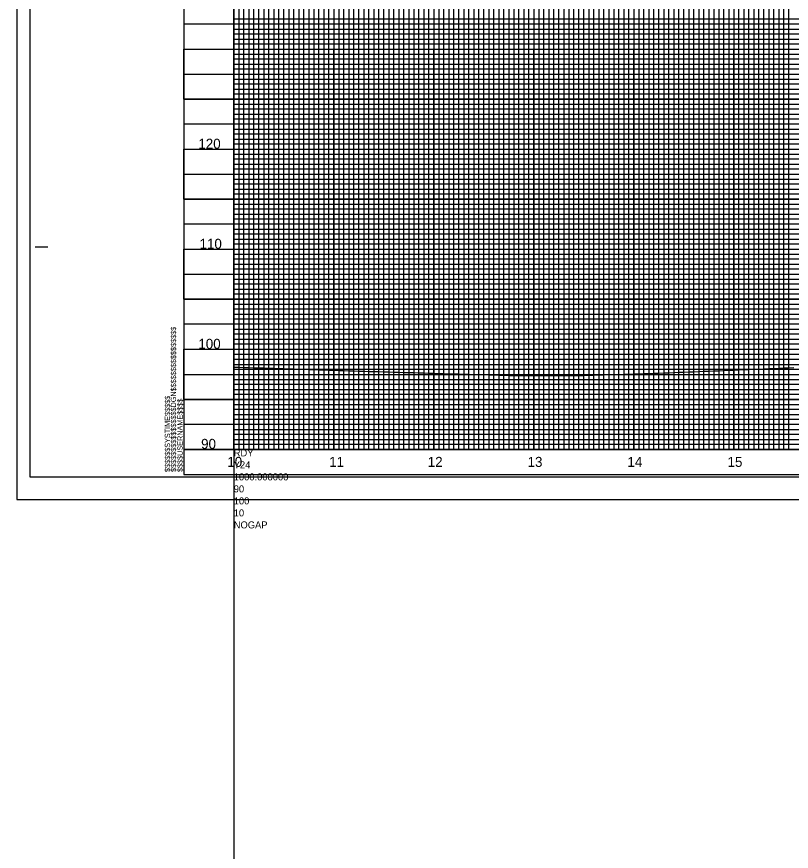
# Model space of a CAD drawing. Extents: x 2345490 to 2436403, y 465165 to 573888.
# Drawn here: x 2381550 to 2382324, y 514736 to 515570 of the extents above; entities that cross this region are included whole.
import ezdxf

# ---------------------------------------------------------------- set-up
doc = ezdxf.new("R2010")
doc.units = 0
for name, color, linetype in [('Old_Level_1', 7, 'Continuous'), ('Old_Level_18', 7, 'Continuous'), ('Old_Level_40', 7, 'Continuous'), ('Old_Level_41', 7, 'Continuous'), ('Old_Level_42', 7, 'Continuous'), ('Old_Level_43', 7, 'Continuous'), ('Old_Level_50', 7, 'Continuous'), ('Old_Level_51', 7, 'Continuous'), ('Old_Level_52', 7, 'Continuous'), ('Old_Level_57', 7, 'Continuous'), ('Old_Level_62', 7, 'Continuous'), ('Old_Level_63', 7, 'Continuous')]:
    doc.layers.add(name, color=color, linetype=linetype)

msp = doc.modelspace()

# ---------------------------------------------------------------- linework, layer by layer
at = {"layer": 'Old_Level_1'}
for points in [[(2381766.799, 515219.7965), (2381771.799, 515219.64425), (2381776.799, 515219.492), (2381781.799, 515219.3395), (2381786.799, 515219.18725), (2381791.799, 515219.03475), (2381796.799, 515218.8825), (2381801.799, 515218.73), (2381806.799, 515218.57775), (2381811.799, 515218.42525), (2381816.799, 515218.27275), (2381821.799, 515218.11875), (2381826.799, 515217.96325), (2381831.799, 515217.80575), (2381836.799, 515217.64675), (2381841.799, 515217.48575), (2381846.799, 515217.32325), (2381851.799, 515217.15875), (2381856.799, 515216.9985), (2381861.799, 515216.833), (2381866.799, 515216.6655), (2381871.799, 515216.49625), (2381876.799, 515216.32525), (2381881.799, 515216.153), (2381886.799, 515215.997), (2381891.799, 515215.8265), (2381896.799, 515215.6525), (2381901.799, 515215.52375), (2381906.799, 515215.3815), (2381911.799, 515215.23825), (2381916.799, 515215.09375), (2381921.799, 515214.948), (2381926.799, 515214.80125), (2381931.799, 515214.66525), (2381936.799, 515214.515), (2381941.799, 515214.36375), (2381946.799, 515214.2115), (2381951.799, 515214.0585), (2381956.799, 515213.90425), (2381961.799, 515213.7525), (2381966.799, 515213.5965), (2381971.799, 515213.4395), (2381976.799, 515213.31125), (2381981.799, 515213.1845), (2381986.799, 515213.0565), (2381991.799, 515212.9185), (2381996.799, 515212.7805), (2382001.799, 515212.6425), (2382006.799, 515212.494), (2382011.799, 515212.35425), (2382016.799, 515212.2145), (2382021.799, 515212.075), (2382026.799, 515211.93575), (2382031.799, 515211.79675), (2382036.799, 515211.65025), (2382041.799, 515211.51175), (2382046.799, 515211.4825), (2382051.799, 515211.4645), (2382056.799, 515211.44675), (2382061.799, 515211.42925), (2382066.799, 515211.41175), (2382071.799, 515211.39125), (2382076.799, 515211.36525), (2382081.799, 515211.34875), (2382086.799, 515211.332), (2382091.799, 515211.3155), (2382096.799, 515211.299), (2382101.799, 515211.2825), (2382106.799, 515211.258), (2382111.799, 515211.2745), (2382116.799, 515211.42925), (2382121.799, 515211.584), (2382126.799, 515211.73875), (2382131.799, 515211.8935), (2382136.799, 515212.04825), (2382141.799, 515212.20225), (2382146.799, 515212.35725), (2382151.799, 515212.51225), (2382156.799, 515212.66575), (2382161.799, 515212.81625), (2382166.799, 515212.9665), (2382171.799, 515213.117), (2382176.799, 515213.2675), (2382181.799, 515213.418), (2382186.799, 515213.58875), (2382191.799, 515213.78875), (2382196.799, 515213.98875), (2382201.799, 515214.18875), (2382206.799, 515214.38875), (2382211.799, 515214.58875), (2382216.799, 515214.788), (2382221.799, 515214.988), (2382226.799, 515215.188), (2382231.799, 515215.388), (2382236.799, 515215.588), (2382241.799, 515215.78825), (2382246.799, 515215.988), (2382251.799, 515216.18825), (2382256.799, 515216.38875), (2382261.799, 515216.598), (2382266.799, 515216.807)], [(2382266.799, 515216.807), (2382271.799, 515217.016), (2382276.799, 515217.22525), (2382281.799, 515217.43425), (2382286.799, 515217.643), (2382291.799, 515217.85225), (2382296.799, 515218.06125), (2382301.799, 515218.27025), (2382306.799, 515218.47925), (2382311.799, 515218.68825), (2382316.799, 515218.897), (2382321.799, 515219.106), (2382326.799, 515219.315)]]:
    msp.add_lwpolyline(points, dxfattribs=at)
at = {"layer": 'Old_Level_18'}
msp.add_line((2381716.79875, 515112.5265), (2381716.79875, 515112.5265), dxfattribs=at)
msp.add_line((2381716.79875, 515112.5265), (2381716.79875, 515112.5265), dxfattribs=at)
msp.add_lwpolyline([(2383216.79875, 516162.5265), (2381716.79875, 516162.5265), (2381716.79875, 515112.5265), (2383216.79875, 515112.5265)], close=True, dxfattribs=at)
at = {"layer": 'Old_Level_40'}
msp.add_line((2381716.79875, 515112.5265), (2381716.79875, 515112.5265), dxfattribs=at)
msp.add_line((2381716.79875, 515112.5265), (2381716.79875, 515112.5265), dxfattribs=at)
msp.add_line((2381716.79875, 515112.5265), (2381716.79875, 515112.5265), dxfattribs=at)
msp.add_line((2381716.79875, 515112.5265), (2381716.79875, 515112.5265), dxfattribs=at)
at = {"layer": 'Old_Level_41'}
for p, q in [((2381568.29875, 515340.0265), (2381580.79875, 515340.0265)), ((2383216.79875, 515137.5265), (2381716.79875, 515137.5265))]:
    msp.add_line(p, q, dxfattribs=at)
for points in [[(2381766.79875, 516162.5265), (2381766.79875, 515137.5265), (2381816.79875, 515137.5265), (2381816.79875, 516162.5265)], [(2381791.79875, 515137.5265), (2381791.79875, 516162.5265)], [(2381841.79875, 516162.5265), (2381841.79875, 515137.5265), (2381891.79875, 515137.5265), (2381891.79875, 516162.5265)], [(2381866.79875, 516162.5265), (2381866.79875, 515137.5265), (2381916.79875, 515137.5265), (2381916.79875, 516162.5265)], [(2381941.79875, 516162.5265), (2381941.79875, 515137.5265), (2381991.79875, 515137.5265), (2381991.79875, 516162.5265)], [(2381966.79875, 516162.5265), (2381966.79875, 515137.5265), (2382016.79875, 515137.5265), (2382016.79875, 516162.5265)], [(2382041.79875, 516162.5265), (2382041.79875, 515137.5265), (2382091.79875, 515137.5265), (2382091.79875, 516162.5265)], [(2382066.79875, 516162.5265), (2382066.79875, 515137.5265), (2382116.79875, 515137.5265), (2382116.79875, 516162.5265)], [(2382141.79875, 516162.5265), (2382141.79875, 515137.5265), (2382191.79875, 515137.5265), (2382191.79875, 516162.5265)], [(2382166.79875, 516162.5265), (2382166.79875, 515137.5265), (2382216.79875, 515137.5265), (2382216.79875, 516162.5265)], [(2382241.79875, 516162.5265), (2382241.79875, 515137.5265), (2382291.79875, 515137.5265), (2382291.79875, 516162.5265)], [(2382266.79875, 516162.5265), (2382266.79875, 515137.5265), (2382316.79875, 515137.5265), (2382316.79875, 516162.5265)], [(2383216.79875, 515562.5265), (2381716.79875, 515562.5265), (2381716.79875, 515512.5265), (2383216.79875, 515512.5265)], [(2383216.79875, 515487.5265), (2381716.79875, 515487.5265), (2381716.79875, 515537.5265), (2383216.79875, 515537.5265)], [(2383216.79875, 515462.5265), (2381716.79875, 515462.5265), (2381716.79875, 515412.5265), (2383216.79875, 515412.5265)], [(2383216.79875, 515387.5265), (2381716.79875, 515387.5265), (2381716.79875, 515437.5265), (2383216.79875, 515437.5265)], [(2383216.79875, 515362.5265), (2381716.79875, 515362.5265), (2381716.79875, 515312.5265), (2383216.79875, 515312.5265)], [(2383216.79875, 515262.5265), (2381716.79875, 515262.5265), (2381716.79875, 515212.5265), (2383216.79875, 515212.5265)], [(2383216.79875, 515187.5265), (2381716.79875, 515187.5265), (2381716.79875, 515237.5265), (2383216.79875, 515237.5265)], [(2383216.79875, 515162.5265), (2381716.79875, 515162.5265)], [(2381754.29875, 515112.5265), (2381754.29875, 515112.5265)]]:
    msp.add_lwpolyline(points, dxfattribs=at)
at = {"layer": 'Old_Level_42'}
msp.add_lwpolyline([(2383216.79875, 515287.5265), (2381716.79875, 515287.5265), (2381716.79875, 515337.5265), (2383216.79875, 515337.5265)], dxfattribs=at)
at = {"layer": 'Old_Level_43'}
for points in [[(2381771.79875, 516162.5265), (2381771.79875, 515137.5265), (2381776.79875, 515137.5265), (2381776.79875, 516162.5265)], [(2381781.79875, 516162.5265), (2381781.79875, 515137.5265), (2381786.79875, 515137.5265), (2381786.79875, 516162.5265)], [(2381796.79875, 516162.5265), (2381796.79875, 515137.5265), (2381801.79875, 515137.5265), (2381801.79875, 516162.5265)], [(2381806.79875, 516162.5265), (2381806.79875, 515137.5265), (2381811.79875, 515137.5265), (2381811.79875, 516162.5265)], [(2381821.79875, 516162.5265), (2381821.79875, 515137.5265), (2381826.79875, 515137.5265), (2381826.79875, 516162.5265)], [(2381831.79875, 516162.5265), (2381831.79875, 515137.5265), (2381836.79875, 515137.5265), (2381836.79875, 516162.5265)], [(2381846.79875, 516162.5265), (2381846.79875, 515137.5265), (2381851.79875, 515137.5265), (2381851.79875, 516162.5265)], [(2381856.79875, 516162.5265), (2381856.79875, 515137.5265), (2381861.79875, 515137.5265), (2381861.79875, 516162.5265)], [(2381871.79875, 516162.5265), (2381871.79875, 515137.5265), (2381876.79875, 515137.5265), (2381876.79875, 516162.5265)], [(2381881.79875, 516162.5265), (2381881.79875, 515137.5265), (2381886.79875, 515137.5265), (2381886.79875, 516162.5265)], [(2381896.79875, 516162.5265), (2381896.79875, 515137.5265), (2381901.79875, 515137.5265), (2381901.79875, 516162.5265)], [(2381906.79875, 516162.5265), (2381906.79875, 515137.5265), (2381911.79875, 515137.5265), (2381911.79875, 516162.5265)], [(2381921.79875, 516162.5265), (2381921.79875, 515137.5265), (2381926.79875, 515137.5265), (2381926.79875, 516162.5265)], [(2381931.79875, 515137.5265), (2381936.79875, 515137.5265), (2381936.79875, 516162.5265)], [(2381931.79875, 516162.5265), (2381931.79875, 515137.5265)], [(2381946.79875, 516162.5265), (2381946.79875, 515137.5265), (2381951.79875, 515137.5265), (2381951.79875, 516162.5265)], [(2381956.79875, 516162.5265), (2381956.79875, 515137.5265), (2381961.79875, 515137.5265), (2381961.79875, 516162.5265)], [(2381971.79875, 516162.5265), (2381971.79875, 515137.5265), (2381976.79875, 515137.5265), (2381976.79875, 516162.5265)], [(2381981.79875, 516162.5265), (2381981.79875, 515137.5265), (2381986.79875, 515137.5265), (2381986.79875, 516162.5265)], [(2381996.79875, 516162.5265), (2381996.79875, 515137.5265), (2382001.79875, 515137.5265), (2382001.79875, 516162.5265)], [(2382006.79875, 516162.5265), (2382006.79875, 515137.5265), (2382011.79875, 515137.5265), (2382011.79875, 516162.5265)], [(2382021.79875, 516162.5265), (2382021.79875, 515137.5265), (2382026.79875, 515137.5265), (2382026.79875, 516162.5265)], [(2382031.79875, 516162.5265), (2382031.79875, 515137.5265), (2382036.79875, 515137.5265), (2382036.79875, 516162.5265)], [(2382046.79875, 516162.5265), (2382046.79875, 515137.5265), (2382051.79875, 515137.5265), (2382051.79875, 516162.5265)], [(2382056.79875, 516162.5265), (2382056.79875, 515137.5265), (2382061.79875, 515137.5265), (2382061.79875, 516162.5265)], [(2382071.79875, 516162.5265), (2382071.79875, 515137.5265), (2382076.79875, 515137.5265), (2382076.79875, 516162.5265)], [(2382081.79875, 516162.5265), (2382081.79875, 515137.5265), (2382086.79875, 515137.5265), (2382086.79875, 516162.5265)], [(2382096.79875, 516162.5265), (2382096.79875, 515137.5265), (2382111.79875, 515137.5265), (2382111.79875, 516162.5265)], [(2382101.79875, 516162.5265), (2382101.79875, 515137.5265), (2382106.79875, 515137.5265), (2382106.79875, 516162.5265)], [(2382101.79875, 516161.9265), (2382101.79875, 515137.5265), (2382106.79875, 515137.5265), (2382106.79875, 516161.9265)], [(2382121.79875, 516162.5265), (2382121.79875, 515137.5265), (2382126.79875, 515137.5265), (2382126.79875, 516162.5265)], [(2382131.79875, 516162.5265), (2382131.79875, 515137.5265), (2382136.79875, 515137.5265), (2382136.79875, 516162.5265)], [(2382146.79875, 516162.5265), (2382146.79875, 515137.5265), (2382151.79875, 515137.5265), (2382151.79875, 516162.5265)], [(2382156.79875, 516162.5265), (2382156.79875, 515137.5265), (2382161.79875, 515137.5265), (2382161.79875, 516162.5265)], [(2382171.79875, 516162.5265), (2382171.79875, 515137.5265), (2382176.79875, 515137.5265), (2382176.79875, 516162.5265)], [(2382181.79875, 516162.5265), (2382181.79875, 515137.5265), (2382186.79875, 515137.5265), (2382186.79875, 516162.5265)], [(2382196.79875, 516162.5265), (2382196.79875, 515137.5265), (2382201.79875, 515137.5265), (2382201.79875, 516162.5265)], [(2382206.79875, 516162.5265), (2382206.79875, 515137.5265), (2382211.79875, 515137.5265), (2382211.79875, 516162.5265)], [(2382221.79875, 516162.5265), (2382221.79875, 515137.5265), (2382226.79875, 515137.5265), (2382226.79875, 516162.5265)], [(2382231.79875, 516162.5265), (2382231.79875, 515137.5265), (2382236.79875, 515137.5265), (2382236.79875, 516162.5265)], [(2382246.79875, 516162.5265), (2382246.79875, 515137.5265)], [(2382251.79875, 516162.5265), (2382251.79875, 515137.5265), (2382256.79875, 515137.5265), (2382256.79875, 516162.5265), (2382261.79875, 516162.5265), (2382261.79875, 515137.5265), (2382271.79875, 515137.5265), (2382271.79875, 516162.5265), (2382276.79875, 516162.5265), (2382276.79875, 515137.5265), (2382281.79875, 515137.5265), (2382281.79875, 516162.5265), (2382286.79875, 516162.5265), (2382286.79875, 515137.5265)], [(2382296.79875, 515137.5265), (2382296.79875, 516162.5265)], [(2382301.79875, 516162.5265), (2382301.79875, 515137.5265), (2382306.79875, 515137.5265), (2382306.79875, 516162.5265)], [(2382311.79875, 516162.5265), (2382311.79875, 515137.5265), (2382321.79875, 515137.5265), (2382321.79875, 516162.5265)], [(2383166.79875, 515567.5265), (2381766.79875, 515567.5265), (2381766.79875, 515557.5265), (2383166.79875, 515557.5265)], [(2383166.79875, 515552.5265), (2381766.79875, 515552.5265), (2381766.79875, 515547.5265), (2383166.79875, 515547.5265)], [(2383166.79875, 515542.5265), (2381766.79875, 515542.5265), (2381766.79875, 515532.5265), (2383166.79875, 515532.5265)], [(2383166.79875, 515527.5265), (2381766.79875, 515527.5265), (2381766.79875, 515522.5265), (2383166.79875, 515522.5265)], [(2383166.79875, 515517.5265), (2381766.79875, 515517.5265), (2381766.79875, 515507.5265), (2383166.79875, 515507.5265)], [(2383166.79875, 515502.5265), (2381766.79875, 515502.5265), (2381766.79875, 515497.5265), (2383166.79875, 515497.5265)], [(2383166.79875, 515492.5265), (2381766.79875, 515492.5265), (2381766.79875, 515482.5265), (2383166.79875, 515482.5265)], [(2383166.79875, 515477.5265), (2381766.79875, 515477.5265), (2381766.79875, 515472.5265), (2383166.79875, 515472.5265)], [(2383166.79875, 515467.5265), (2381766.79875, 515467.5265), (2381766.79875, 515457.5265), (2383166.79875, 515457.5265)], [(2383166.79875, 515452.5265), (2381766.79875, 515452.5265), (2381766.79875, 515447.5265), (2383166.79875, 515447.5265)], [(2383166.79875, 515442.5265), (2381766.79875, 515442.5265), (2381766.79875, 515432.5265), (2383166.79875, 515432.5265)], [(2383166.79875, 515427.5265), (2381766.79875, 515427.5265), (2381766.79875, 515422.5265), (2383166.79875, 515422.5265)], [(2383166.79875, 515417.5265), (2381766.79875, 515417.5265), (2381766.79875, 515407.5265), (2383166.79875, 515407.5265)], [(2383166.79875, 515402.5265), (2381766.79875, 515402.5265), (2381766.79875, 515397.5265), (2383166.79875, 515397.5265)], [(2383166.79875, 515392.5265), (2381766.79875, 515392.5265), (2381766.79875, 515382.5265), (2383166.79875, 515382.5265)], [(2383166.79875, 515377.5265), (2381766.79875, 515377.5265), (2381766.79875, 515372.5265), (2383166.79875, 515372.5265)], [(2383166.79875, 515367.5265), (2381766.79875, 515367.5265), (2381766.79875, 515357.5265), (2383166.79875, 515357.5265)], [(2383166.79875, 515352.5265), (2381766.79875, 515352.5265), (2381766.79875, 515347.5265), (2383166.79875, 515347.5265)], [(2383166.79875, 515342.5265), (2381766.79875, 515342.5265)], [(2381766.79875, 515332.5265), (2383166.79875, 515332.5265)], [(2383166.79875, 515327.5265), (2381766.79875, 515327.5265), (2381766.79875, 515322.5265), (2383166.79875, 515322.5265)], [(2383166.79875, 515317.5265), (2381766.79875, 515317.5265)], [(2381766.79875, 515307.5265), (2383166.79875, 515307.5265)], [(2383166.79875, 515302.5265), (2381766.79875, 515302.5265), (2381766.79875, 515297.5265), (2383166.79875, 515297.5265)], [(2383166.79875, 515292.5265), (2381766.79875, 515292.5265), (2381766.79875, 515282.5265), (2383166.79875, 515282.5265)], [(2383166.79875, 515277.5265), (2381766.79875, 515277.5265), (2381766.79875, 515272.5265), (2383166.79875, 515272.5265)], [(2383166.79875, 515267.5265), (2381766.79875, 515267.5265), (2381766.79875, 515257.5265), (2383166.79875, 515257.5265)], [(2383166.79875, 515252.5265), (2381766.79875, 515252.5265), (2381766.79875, 515247.5265), (2383166.79875, 515247.5265)], [(2383166.79875, 515242.5265), (2381766.79875, 515242.5265), (2381766.79875, 515232.5265), (2383166.79875, 515232.5265)], [(2383166.79875, 515227.5265), (2381766.79875, 515227.5265), (2381766.79875, 515222.5265), (2383166.79875, 515222.5265)], [(2383166.79875, 515217.5265), (2381766.79875, 515217.5265), (2381766.79875, 515207.5265), (2383166.79875, 515207.5265)], [(2383166.79875, 515202.5265), (2381766.79875, 515202.5265), (2381766.79875, 515197.5265), (2383166.79875, 515197.5265)], [(2383166.79875, 515192.5265), (2381766.79875, 515192.5265), (2381766.79875, 515182.5265), (2383166.79875, 515182.5265)], [(2383166.79875, 515177.5265), (2381766.79875, 515177.5265), (2381766.79875, 515172.5265), (2383166.79875, 515172.5265)], [(2383166.79875, 515167.5265), (2381766.79875, 515167.5265), (2381766.79875, 515157.5265), (2383166.79875, 515157.5265)], [(2383166.79875, 515152.5265), (2381766.79875, 515152.5265), (2381766.79875, 515147.5265), (2383166.79875, 515147.5265)], [(2383166.79875, 515142.5265), (2381766.79875, 515142.5265)]]:
    msp.add_lwpolyline(points, dxfattribs=at)
at = {"layer": 'Old_Level_50'}
msp.add_line((2381549.79875, 515087.5265), (2381549.79875, 515087.5265), dxfattribs=at)
msp.add_lwpolyline([(2383229.29875, 516165.0765), (2381562.79875, 516165.0765), (2381562.79875, 515109.9765), (2383229.29875, 515109.9765)], close=True, dxfattribs=at)
at = {"layer": 'Old_Level_51'}
msp.add_lwpolyline([(2383233.79875, 516187.5265), (2381549.79875, 516187.5265), (2381549.79875, 515087.5265), (2383233.79875, 515087.5265)], close=True, dxfattribs=at)
at = {"layer": 'Old_Level_52'}
msp.add_line((2381562.79875, 515109.9765), (2381562.79875, 515109.9765), dxfattribs=at)
at = {"layer": 'Old_Level_57'}
for p, q in [((2381716.79925, 515537.52675), (2386366.79875, 515537.52675)), ((2381766.79875, 515137.52675), (2381766.79875, 515537.52675)), ((2381866.79875, 515137.52675), (2381866.79875, 515537.52675)), ((2381966.79875, 515137.52675), (2381966.79875, 515537.52675)), ((2382066.79875, 515137.52675), (2382066.79875, 515537.52675)), ((2382166.79875, 515137.52675), (2382166.79875, 515537.52675)), ((2382166.79875, 515137.62675), (2382166.79875, 515537.52675)), ((2382266.79875, 515137.52675), (2382266.79875, 515537.52675)), ((2382266.79875, 515137.62675), (2382266.79875, 515537.52675)), ((2381716.79925, 515487.52675), (2386366.79875, 515487.52675)), ((2381716.79925, 515437.52675), (2386366.79875, 515437.52675)), ((2381716.79925, 515387.52675), (2386366.79875, 515387.52675)), ((2381716.79925, 515337.52675), (2386366.79875, 515337.52675)), ((2381716.79925, 515287.52675), (2386366.79875, 515287.52675)), ((2381716.79925, 515237.52675), (2386366.79875, 515237.52675)), ((2381716.799, 515187.52675), (2386366.79875, 515187.52675)), ((2381716.79925, 515137.52675), (2386366.79875, 515137.52675))]:
    msp.add_line(p, q, dxfattribs=at)
at = {"layer": 'Old_Level_63'}
for q in [(2381766.79875, 517637.5265), (2386228.05125, 515137.5265), (2381766.79875, 512637.5265)]:
    msp.add_line((2381766.79875, 515137.5265), q, dxfattribs=at)

# ---------------------------------------------------------------- texts
at = {"layer": 'Old_Level_41'}
for s, p in [('$$$$$$$$$$$$$$$$DGN$$$$$$$$$$$$$$$$', (2381709.14875, 515114.889)), ('$$$$$$SYSTIME$$$$$', (2381703.09875, 515114.889)), ('$$$$USERNAME$$$$', (2381715.72375, 515114.9015))]:
    msp.add_text(s, height=5.25, rotation=90, dxfattribs=at).set_placement(p)
at = {"layer": 'Old_Level_62'}
for s, p in [('120', (2381731.428, 515438.0265)), ('110', (2381732.62475, 515338.0265)), ('100', (2381731.428, 515238.0265)), ('90', (2381734.1855, 515138.0265)), ('10', (2381760.3825, 515120.0265)), ('11', (2381862.222, 515120.0265)), ('12', (2381960.77025, 515120.0265)), ('13', (2382060.605, 515120.0265)), ('14', (2382160.4475, 515120.0265)), ('15', (2382260.54, 515120.0265))]:
    msp.add_text(s, height=10.000001, dxfattribs=at).set_placement(p)
at = {"layer": 'Old_Level_63'}
for s, height, p in [('RDY', 7.000001, (2381766.79875, 515130.5265)), ('Y24', 7.000001, (2381766.79875, 515118.5265)), ('1000.000000', 7.0000005, (2381766.79875, 515106.5265)), ('90', 7.000001, (2381766.79875, 515094.5265)), ('100', 7.000001, (2381766.79875, 515082.5265)), ('10', 7.000001, (2381766.79875, 515070.5265)), ('NOGAP', 7.000001, (2381766.79875, 515058.5265))]:
    msp.add_text(s, height=height, dxfattribs=at).set_placement(p)

doc.saveas('drawing.dxf')
